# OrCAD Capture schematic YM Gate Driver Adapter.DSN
size A; title: Hybrid Pack Gate Driver Adapter; rev: 0; note: Hybrid Pack Gate Driver Adapter
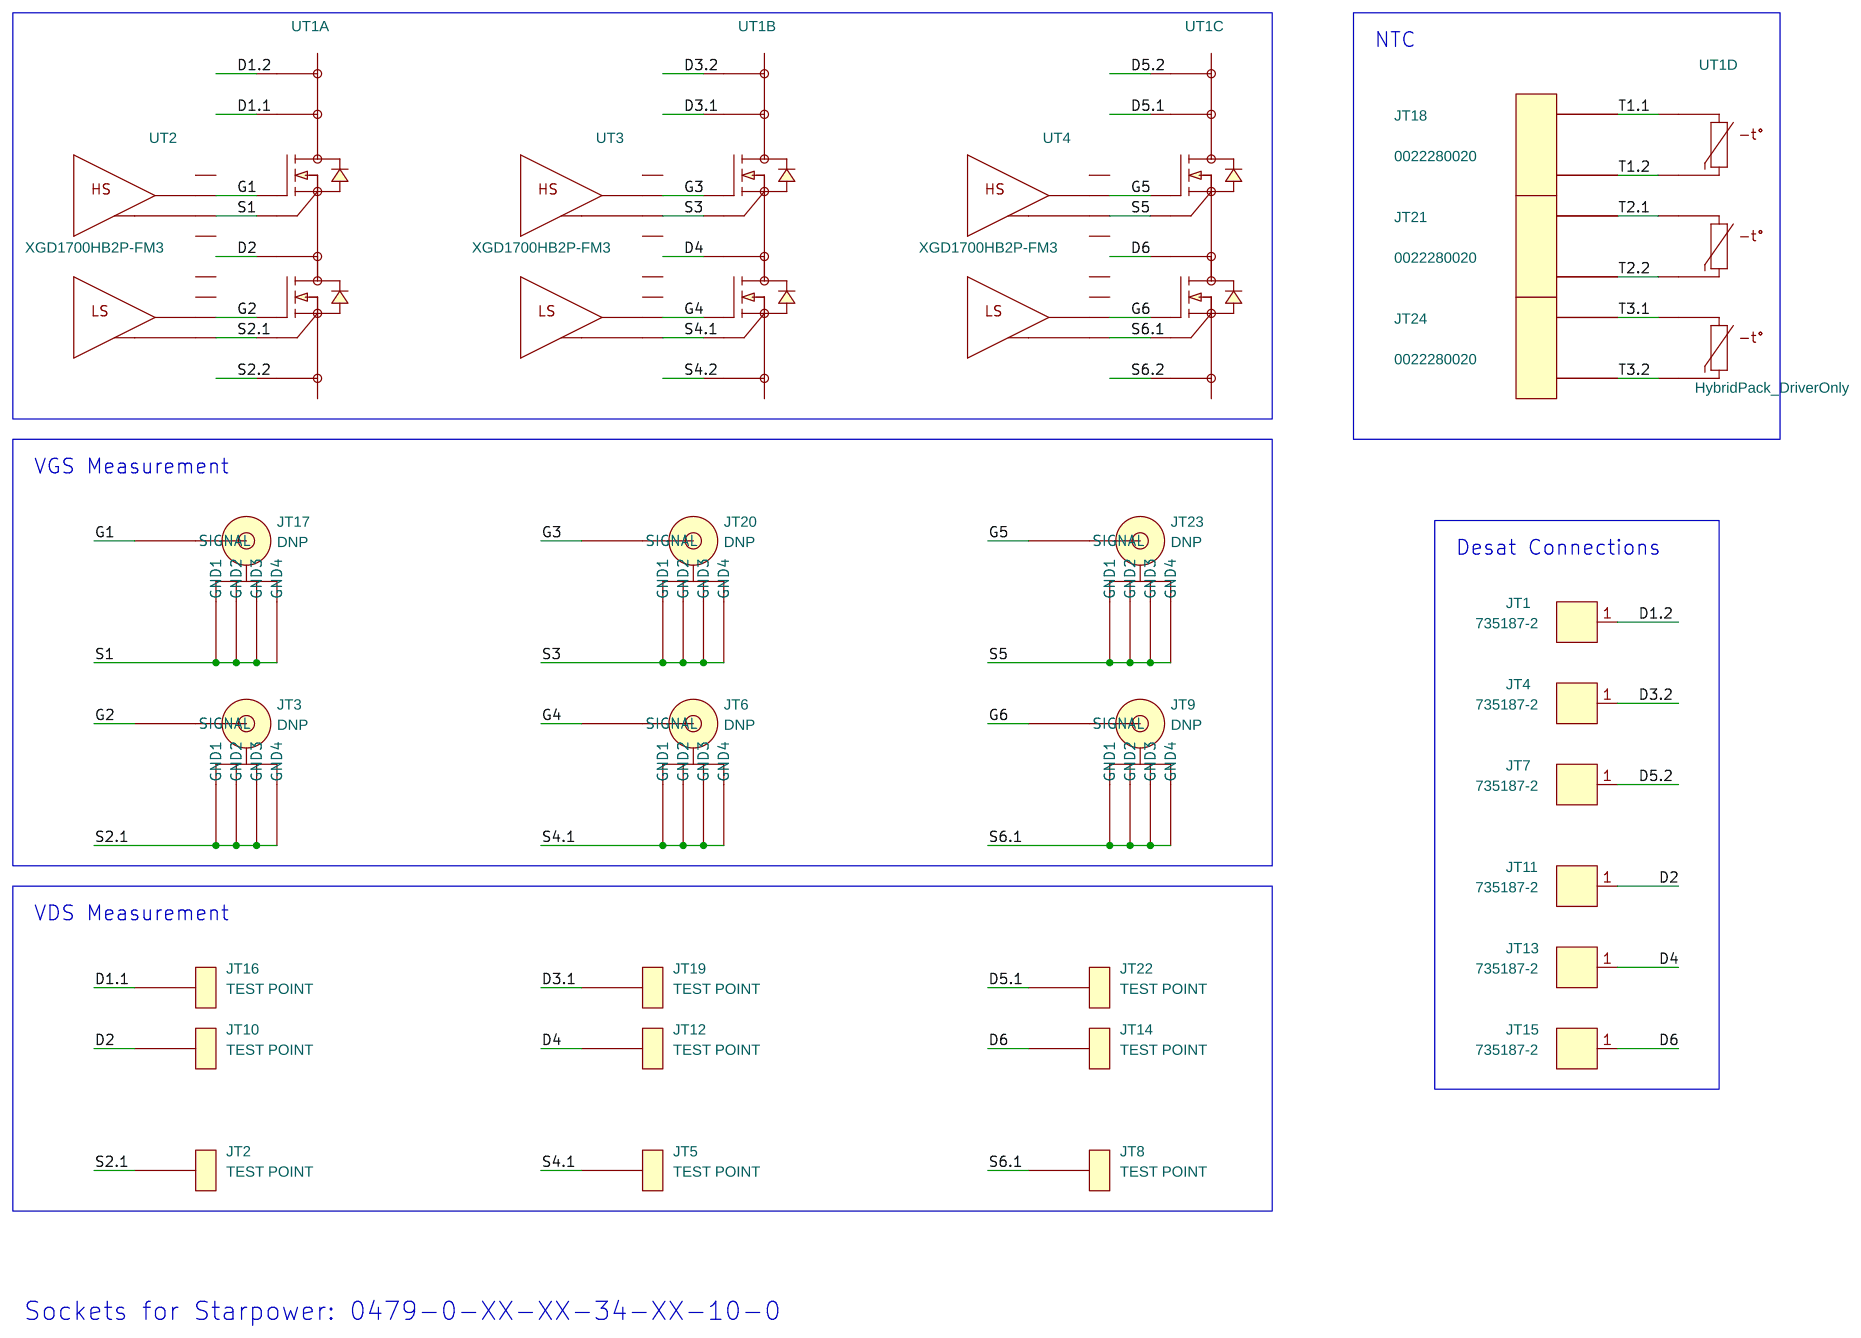
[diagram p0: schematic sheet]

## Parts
JT1  735187-2  [con_1x1_63mil]
JT2  TEST POINT  [con1_TP]
JT3  DNP  [MMCX_PLUG_TH]
JT4  735187-2  [con_1x1_63mil]
JT5  TEST POINT  [con1_TP]
JT6  DNP  [MMCX_PLUG_TH]
JT7  735187-2  [con_1x1_63mil]
JT8  TEST POINT  [con1_TP]
JT9  DNP  [MMCX_PLUG_TH]
JT10  TEST POINT  [con1_TP]
JT11  735187-2  [con_1x1_63mil]
JT12  TEST POINT  [con1_TP]
JT13  735187-2  [con_1x1_63mil]
JT14  TEST POINT  [con1_TP]
JT15  735187-2  [con_1x1_63mil]
JT16  TEST POINT  [con1_TP]
JT17  DNP  [MMCX_PLUG_TH]
JT18  0022280020  [CONN_HEADER_2POS_LOCKING]
JT19  TEST POINT  [con1_TP]
JT20  DNP  [MMCX_PLUG_TH]
JT21  0022280020  [CONN_HEADER_2POS_LOCKING]
JT22  TEST POINT  [con1_TP]
JT23  DNP  [MMCX_PLUG_TH]
JT24  0022280020  [CONN_HEADER_2POS_LOCKING]
UT1  HybridPack_DriverOnly  [HybridPack_DriverOnly]  (sections A,B,C,D)
UT2  XGD1700HB2P-FM3  [XGD1700HB2P-FM3_NoMiddleMount]
UT3  XGD1700HB2P-FM3  [XGD1700HB2P-FM3_NoMiddleMount]
UT4  XGD1700HB2P-FM3  [XGD1700HB2P-FM3_NoMiddleMount]

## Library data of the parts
JT1 JT4 JT7 JT11 JT13 JT15 = HDR_1X1_M: CONN QC TAB 0.110 SOLDER; CLASS: IO; Company Part Status: New; Manufacturer: TE Connectivity AMP Connectors; PART_NUMBER: TMP-635
JT2 JT5 JT8 JT10 JT12 JT14 JT16 JT19 JT22 = TEST_POINT
JT3 JT6 JT9 JT17 JT20 JT23 = BNC_5P: CONN MMCX JACK R/A 50 OHM PCB; CLASS: IO; Manufacturer: Samtec Inc.; Manufacturer PN: MMCX-J-P-H-RA-TH1; PART_NUMBER: TMP-1484
JT18 JT21 JT24 = 0022280020
UT1 = HybridPack_DriverOnly_2
UT2-UT4 = XGD1700HB2P-FM3

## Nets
D1.1: JT16.1 UT1.2(D1.1)
D1.2: JT1.1 UT1.1(D1.2)
D2: JT10.1 JT11.1 UT1.5(D2)
D3.1: JT19.1 UT1.10(D3.1)
D3.2: JT4.1 UT1.9(D3.2)
D4: JT12.1 JT13.1 UT1.13(D4)
D5.1: JT22.1 UT1.18(D5.1)
D5.2: JT7.1 UT1.17(D5.2)
D6: JT14.1 JT15.1 UT1.21(D6)
G1: JT17.1(SIGNAL) UT1.3(G1) UT2.1(HS-Gate)
G2: JT3.1(SIGNAL) UT1.6(G2) UT2.3(LS-Gate)
G3: JT20.1(SIGNAL) UT1.11(G3) UT3.1(HS-Gate)
G4: JT6.1(SIGNAL) UT1.14(G4) UT3.3(LS-Gate)
G5: JT23.1(SIGNAL) UT1.19(G5) UT4.1(HS-Gate)
G6: JT9.1(SIGNAL) UT1.22(G6) UT4.3(LS-Gate)
S1: JT17.2(GND1) JT17.3(GND2) JT17.4(GND3) JT17.5(GND4) UT1.4(S1) UT2.2(HS-Source)
S2.1: JT2.1 JT3.2(GND1) JT3.3(GND2) JT3.4(GND3) JT3.5(GND4) UT1.7(S2.1) UT2.4(LS-Source)
S2.2: UT1.8(S2.2)
S3: JT20.2(GND1) JT20.3(GND2) JT20.4(GND3) JT20.5(GND4) UT1.12(S3) UT3.2(HS-Source)
S4.1: JT5.1 JT6.2(GND1) JT6.3(GND2) JT6.4(GND3) JT6.5(GND4) UT1.15(S4.1) UT3.4(LS-Source)
S4.2: UT1.16(S4.2)
S5: JT23.2(GND1) JT23.3(GND2) JT23.4(GND3) JT23.5(GND4) UT1.20(S5) UT4.2(HS-Source)
S6.1: JT8.1 JT9.2(GND1) JT9.3(GND2) JT9.4(GND3) JT9.5(GND4) UT1.23(S6.1) UT4.4(LS-Source)
S6.2: UT1.24(S6.2)
T1.1: JT18.2 UT1.25(T1.1)
T1.2: JT18.1 UT1.26(T1.2)
T2.1: JT21.2 UT1.27(T2.1)
T2.2: JT21.1 UT1.28(T2.2)
T3.1: JT24.2 UT1.29(T3.1)
T3.2: JT24.1 UT1.30(T3.2)

Not connected (* = marked no-connect by the designer): UT2 12(HS-Gate-2) 22(HS-Source-2) 32(LS-Gate-2) 42(LS-Source-2); UT3 12(HS-Gate-2) 22(HS-Source-2) 32(LS-Gate-2) 42(LS-Source-2); UT4 12(HS-Gate-2) 22(HS-Source-2) 32(LS-Gate-2) 42(LS-Source-2)

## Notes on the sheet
- NTC
- VGS Measurement
- Desat Connections
- VDS Measurement
- Sockets for Starpower: 0479-0-XX-XX-34-XX-10-0
